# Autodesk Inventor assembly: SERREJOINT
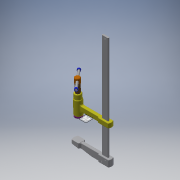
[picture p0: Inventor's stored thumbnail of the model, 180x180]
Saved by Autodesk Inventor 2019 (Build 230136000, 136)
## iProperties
Created: 2019-02
Part Number: SERREJOINT
Material: Générique
Document SubType Name: Assembly
Designer: si-nd67
Author: si-nd67
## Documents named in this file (6)
- E:\ECAM\serrejointsw\SERREJOINT.iam
- E:\ECAM\serrejointsw\SEA-serrej.iam
- E:\ECAM\serrejointsw\SEB-serrej.iam
- E:\ECAM\serrejointsw\SEC-serrej.iam
- E:\ECAM\serrejointsw\Piston14.ipt
- E:\ECAM\serrejointsw\Vis de manoeuvre14.ipt
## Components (5 placed, 5 different names)
1. SEA-serrej:1 [sub-assembly] — Placage:2, Placage:5, position mors Mob et fixe
2. SEB-serrej:1 [sub-assembly] — Placage:1, Placage:10
3. SEC-serrej:1 [sub-assembly] — Placage:2, Placage:5, Angle:1, Placage:6, Placage:7, contact piston mors mobile
4. Piston14:1 — Angle:1, Placage:6, Placage:8, contact piston mors mobile, contact vis -Piston, position mors Mob et fixe
5. Vis de manoeuvre14:1 — Placage:1, Placage:7, Placage:8, contact vis -Piston, Placage:10
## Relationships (11: Mate 8, Insert 2, Angle 1)
- Placage:1 [Mate]: SEB-serrej:1 ↔ Vis de manoeuvre14:1
- Placage:2 [Mate]: SEA-serrej:1 ↔ SEC-serrej:1
- Placage:5 [Mate]: SEA-serrej:1 ↔ SEC-serrej:1
- Angle:1: SEC-serrej:1 ↔ Piston14:1
- Placage:6 [Mate]: SEC-serrej:1 ↔ Piston14:1
- Placage:7 [Mate]: SEC-serrej:1 ↔ Vis de manoeuvre14:1
- Placage:8 [Mate]: Piston14:1 ↔ Vis de manoeuvre14:1
- contact piston mors mobile [Insert]: SEC-serrej:1 ↔ Piston14:1
- contact vis -Piston [Insert]: Piston14:1 ↔ Vis de manoeuvre14:1
- position mors Mob et fixe [Mate]: SEA-serrej:1 ↔ Piston14:1
- Placage:10 [Mate]: SEB-serrej:1 ↔ Vis de manoeuvre14:1
